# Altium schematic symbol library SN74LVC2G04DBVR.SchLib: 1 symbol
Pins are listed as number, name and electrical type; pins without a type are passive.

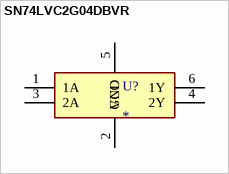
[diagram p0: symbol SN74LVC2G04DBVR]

## SN74LVC2G04DBVR
designator U?
2-ch, 1.65-V to 5.5-V inverters; MF: Texas Instruments; MP: SN74LVC2G04DBVR
footprint SOT95P280X145-6N
pins: 1 1A, 2 GND, 3 2A, 4 2Y, 5 VCC, 6 1Y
